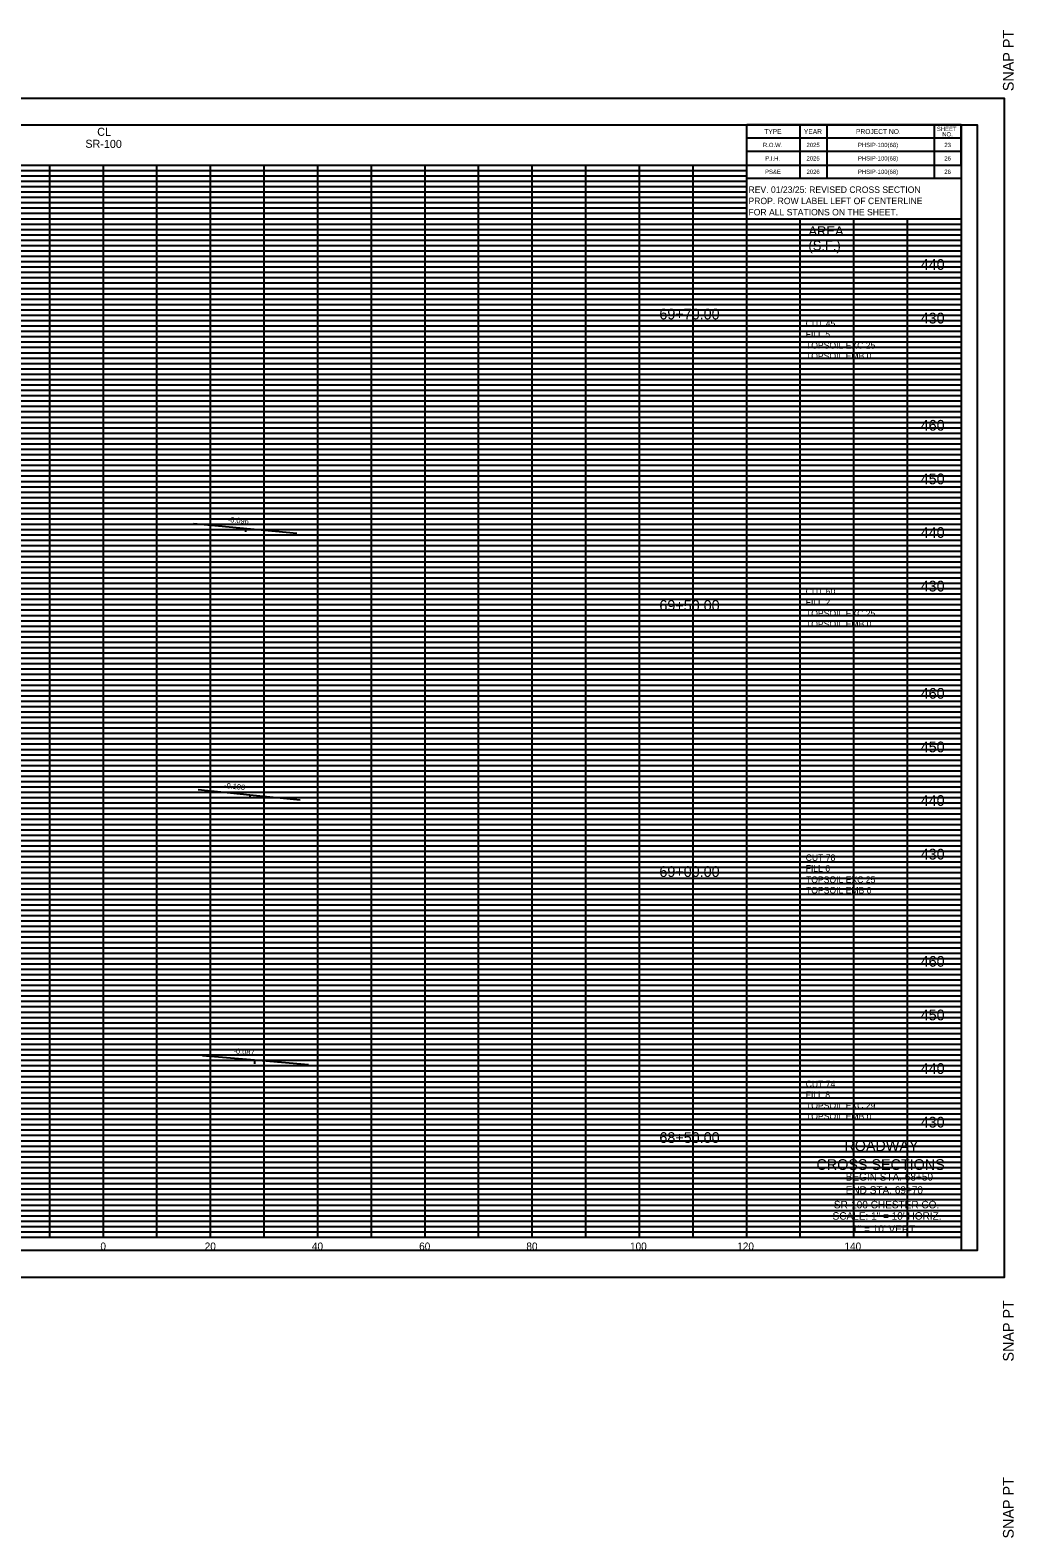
# Model space of a CAD drawing. Extents: x 37 to 1710, y 707 to 2305.
# Drawn here: x 1526.3 to 1709.8, y 1213.9 to 1495.2 of the extents above; entities that cross this region are included whole.
import ezdxf

# ---------------------------------------------------------------- set-up
doc = ezdxf.new("R2010")
doc.units = 0
for name, color, linetype in [('DESIGN - DRAINAGE - Special Ditch Width Text', 7, 'Continuous'), ('DESIGN - SCRATCH - User 1', 7, 'Continuous'), ('DESIGN - SHEET - Corner Text', 7, 'Continuous'), ('DESIGN - SHEET - Light Grid', 7, 'Continuous'), ('DESIGN - SHEET - Linework', 7, 'Continuous'), ('DESIGN - SHEET - Plot Shape', 7, 'Continuous'), ('DESIGN - TITLE SHEET - PROJECT LENGTH - ROW', 7, 'Continuous'), ('DESIGN - TYPICAL - Finished Grade and Subgrade', 7, 'Continuous'), ('DESIGN - TYPICAL - Finished Grade Slopes Text', 7, 'Continuous'), ('DESIGN - TYPICAL - Text', 7, 'Continuous')]:
    doc.layers.add(name, color=color, linetype=linetype)

msp = doc.modelspace()

# ---------------------------------------------------------------- linework, layer by layer
at = {"layer": 'DESIGN - SCRATCH - User 1'}
for p, q in [((1665, 1473.75), (1665, 1473.75)), ((1665, 1471.25), (1665, 1471.25)), ((1672.5, 1473.75), (1672.5, 1473.75)), ((1672.5, 1471.25), (1672.5, 1471.25)), ((1685, 1473.75), (1685, 1473.75)), ((1685, 1471.25), (1685, 1471.25)), ((1697.5, 1473.75), (1697.5, 1473.75)), ((1697.5, 1471.25), (1697.5, 1471.25))]:
    msp.add_line(p, q, dxfattribs=at)
at = {"layer": 'DESIGN - SHEET - Light Grid'}
for p, q in [((1380, 1469), (1660, 1469)), ((1380, 1468), (1660, 1468)), ((1380, 1467), (1660, 1467)), ((1380, 1466), (1660, 1466)), ((1380, 1465), (1660, 1465)), ((1380, 1464), (1660, 1464)), ((1380, 1463), (1660, 1463)), ((1380, 1462), (1660, 1462)), ((1380, 1461), (1660, 1461)), ((1380, 1459), (1700, 1459)), ((1380, 1458), (1700, 1458)), ((1380, 1457), (1700, 1457)), ((1380, 1456), (1700, 1456)), ((1380, 1455), (1700, 1455)), ((1380, 1454), (1700, 1454)), ((1380, 1453), (1700, 1453)), ((1380, 1452), (1700, 1452)), ((1380, 1451), (1700, 1451)), ((1380, 1449), (1700, 1449)), ((1380, 1448), (1700, 1448)), ((1380, 1447), (1700, 1447)), ((1380, 1446), (1700, 1446)), ((1380, 1445), (1700, 1445)), ((1380, 1444), (1700, 1444)), ((1380, 1443), (1700, 1443)), ((1380, 1442), (1700, 1442)), ((1380, 1441), (1700, 1441)), ((1380, 1439), (1700, 1439)), ((1380, 1438), (1700, 1438)), ((1380, 1437), (1700, 1437)), ((1380, 1436), (1700, 1436)), ((1380, 1435), (1700, 1435)), ((1380, 1434), (1700, 1434)), ((1380, 1433), (1700, 1433)), ((1380, 1432), (1700, 1432)), ((1380, 1431), (1700, 1431)), ((1380, 1429), (1700, 1429)), ((1380, 1428), (1700, 1428)), ((1380, 1427), (1700, 1427)), ((1380, 1426), (1700, 1426)), ((1380, 1425), (1700, 1425)), ((1380, 1424), (1700, 1424)), ((1380, 1423), (1700, 1423)), ((1380, 1422), (1700, 1422)), ((1380, 1421), (1700, 1421)), ((1380, 1419), (1700, 1419)), ((1380, 1418), (1700, 1418)), ((1380, 1417), (1700, 1417)), ((1380, 1416), (1700, 1416)), ((1380, 1415), (1700, 1415)), ((1380, 1414), (1700, 1414)), ((1380, 1413), (1700, 1413)), ((1380, 1412), (1700, 1412)), ((1380, 1411), (1700, 1411)), ((1380, 1409), (1700, 1409)), ((1380, 1408), (1700, 1408)), ((1380, 1407), (1700, 1407)), ((1380, 1406), (1700, 1406)), ((1380, 1405), (1700, 1405)), ((1380, 1404), (1700, 1404)), ((1380, 1403), (1700, 1403)), ((1380, 1402), (1700, 1402)), ((1380, 1401), (1700, 1401)), ((1380, 1399), (1700, 1399)), ((1380, 1398), (1700, 1398)), ((1380, 1397), (1700, 1397)), ((1380, 1396), (1700, 1396)), ((1380, 1395), (1700, 1395)), ((1380, 1394), (1700, 1394)), ((1380, 1393), (1700, 1393)), ((1380, 1392), (1700, 1392)), ((1380, 1391), (1700, 1391)), ((1380, 1389), (1700, 1389)), ((1380, 1388), (1700, 1388)), ((1380, 1387), (1700, 1387)), ((1380, 1386), (1700, 1386)), ((1380, 1385), (1700, 1385)), ((1380, 1384), (1700, 1384)), ((1380, 1383), (1700, 1383)), ((1380, 1382), (1700, 1382)), ((1380, 1381), (1700, 1381)), ((1380, 1379), (1700, 1379)), ((1380, 1378), (1700, 1378)), ((1380, 1377), (1700, 1377)), ((1380, 1376), (1700, 1376)), ((1380, 1375), (1700, 1375)), ((1380, 1374), (1700, 1374)), ((1380, 1373), (1700, 1373)), ((1380, 1372), (1700, 1372)), ((1380, 1371), (1700, 1371)), ((1380, 1369), (1700, 1369)), ((1380, 1368), (1700, 1368)), ((1380, 1367), (1700, 1367)), ((1380, 1366), (1700, 1366)), ((1380, 1365), (1700, 1365)), ((1380, 1364), (1700, 1364)), ((1380, 1363), (1700, 1363)), ((1380, 1362), (1700, 1362)), ((1380, 1361), (1700, 1361)), ((1380, 1359), (1700, 1359)), ((1380, 1358), (1700, 1358)), ((1380, 1357), (1700, 1357)), ((1380, 1356), (1700, 1356)), ((1380, 1355), (1700, 1355)), ((1380, 1354), (1700, 1354)), ((1380, 1353), (1700, 1353)), ((1380, 1352), (1700, 1352)), ((1380, 1351), (1700, 1351)), ((1380, 1349), (1700, 1349)), ((1380, 1348), (1700, 1348)), ((1380, 1347), (1700, 1347)), ((1380, 1346), (1700, 1346)), ((1380, 1345), (1700, 1345)), ((1380, 1344), (1700, 1344)), ((1380, 1343), (1700, 1343)), ((1380, 1342), (1700, 1342)), ((1380, 1341), (1700, 1341)), ((1380, 1339), (1700, 1339)), ((1380, 1338), (1700, 1338)), ((1380, 1337), (1700, 1337)), ((1380, 1336), (1700, 1336)), ((1380, 1335), (1700, 1335)), ((1380, 1334), (1700, 1334)), ((1380, 1333), (1700, 1333)), ((1380, 1332), (1700, 1332)), ((1380, 1331), (1700, 1331)), ((1380, 1329), (1700, 1329)), ((1380, 1328), (1700, 1328)), ((1380, 1327), (1700, 1327)), ((1380, 1326), (1700, 1326)), ((1380, 1325), (1700, 1325)), ((1380, 1324), (1700, 1324)), ((1380, 1323), (1700, 1323)), ((1380, 1322), (1700, 1322)), ((1380, 1321), (1700, 1321)), ((1380, 1319), (1700, 1319)), ((1380, 1318), (1700, 1318)), ((1380, 1317), (1700, 1317)), ((1380, 1316), (1700, 1316)), ((1380, 1315), (1700, 1315)), ((1380, 1314), (1700, 1314)), ((1380, 1313), (1700, 1313)), ((1380, 1312), (1700, 1312)), ((1380, 1311), (1700, 1311)), ((1380, 1309), (1700, 1309)), ((1380, 1308), (1700, 1308)), ((1380, 1307), (1700, 1307)), ((1380, 1306), (1700, 1306)), ((1380, 1305), (1700, 1305)), ((1380, 1304), (1700, 1304)), ((1380, 1303), (1700, 1303)), ((1380, 1302), (1700, 1302)), ((1380, 1301), (1700, 1301)), ((1380, 1299), (1700, 1299)), ((1380, 1298), (1700, 1298)), ((1380, 1297), (1700, 1297)), ((1380, 1296), (1700, 1296)), ((1380, 1295), (1700, 1295)), ((1380, 1294), (1700, 1294)), ((1380, 1293), (1700, 1293)), ((1380, 1292), (1700, 1292)), ((1380, 1291), (1700, 1291)), ((1380, 1289), (1700, 1289)), ((1380, 1288), (1700, 1288)), ((1380, 1287), (1700, 1287)), ((1380, 1286), (1700, 1286)), ((1380, 1285), (1700, 1285)), ((1380, 1284), (1700, 1284)), ((1380, 1283), (1700, 1283)), ((1380, 1282), (1700, 1282)), ((1380, 1281), (1700, 1281)), ((1380, 1279), (1700, 1279)), ((1380, 1278), (1700, 1278)), ((1380, 1277), (1700, 1277)), ((1380, 1276), (1700, 1276)), ((1380, 1275), (1700, 1275)), ((1380, 1274), (1700, 1274)), ((1380, 1273), (1700, 1273)), ((1380, 1272), (1700, 1272)), ((1380, 1271), (1700, 1271))]:
    msp.add_line(p, q, dxfattribs=at)
at = {"layer": 'DESIGN - SHEET - Linework'}
for p, q in [((1700, 1477.5), (1660, 1477.5)), ((1660, 1470), (1660, 1477.5)), ((1670, 1467.5), (1670, 1477.5)), ((1675, 1467.5), (1675, 1477.5)), ((1695, 1467.5), (1695, 1477.5)), ((1700, 1470), (1700, 1477.5)), ((1700, 1475), (1660, 1475)), ((1700, 1472.5), (1660, 1472.5)), ((1380, 1470), (1700, 1470)), ((1530, 1270), (1530, 1470)), ((1540, 1270), (1540, 1470)), ((1550, 1270), (1550, 1470)), ((1560, 1270), (1560, 1470)), ((1570, 1270), (1570, 1470)), ((1580, 1270), (1580, 1470)), ((1590, 1270), (1590, 1470)), ((1600, 1270), (1600, 1470)), ((1610, 1270), (1610, 1470)), ((1620, 1270), (1620, 1470)), ((1630, 1270), (1630, 1470)), ((1640, 1270), (1640, 1470)), ((1650, 1270), (1650, 1470)), ((1660, 1270), (1660, 1470)), ((1700, 1467.5), (1660, 1467.5)), ((1380, 1460), (1700, 1460)), ((1670, 1270), (1670, 1460)), ((1680, 1270), (1680, 1460)), ((1690, 1270), (1690, 1460)), ((1380, 1450), (1700, 1450)), ((1380, 1440), (1700, 1440)), ((1380, 1430), (1700, 1430)), ((1380, 1420), (1700, 1420)), ((1380, 1410), (1700, 1410)), ((1380, 1400), (1700, 1400)), ((1380, 1390), (1700, 1390)), ((1380, 1380), (1700, 1380)), ((1380, 1370), (1700, 1370)), ((1380, 1360), (1700, 1360)), ((1380, 1350), (1700, 1350)), ((1380, 1340), (1700, 1340)), ((1380, 1330), (1700, 1330)), ((1380, 1320), (1700, 1320)), ((1380, 1310), (1700, 1310)), ((1380, 1300), (1700, 1300)), ((1380, 1290), (1700, 1290)), ((1380, 1280), (1700, 1280)), ((1380, 1270), (1700, 1270))]:
    msp.add_line(p, q, dxfattribs=at)
for points in [[(1368, 1482.5), (1708, 1482.5), (1708, 1262.5), (1368, 1262.5)], [(1380, 1477.5), (1700, 1477.5), (1700, 1267.5), (1380, 1267.5)]]:
    msp.add_lwpolyline(points, close=True, dxfattribs=at)
at = {"layer": 'DESIGN - SHEET - Plot Shape'}
msp.add_lwpolyline([(1373, 1477.5), (1703, 1477.5), (1703, 1267.5), (1373, 1267.5)], close=True, dxfattribs=at)
at = {"layer": 'DESIGN - TYPICAL - Finished Grade and Subgrade'}
for p, q in [((1556.84, 1403.16), (1576.09, 1401.31)), ((1566.52, 1402.23), (1566.52, 1401.55)), ((1557.67, 1353.51), (1567.35, 1352.54)), ((1567.35, 1352.54), (1567.35, 1351.9)), ((1567.35, 1352.54), (1576.7, 1351.61)), ((1558.5, 1303.92), (1568.18, 1303.08)), ((1568.18, 1303.08), (1568.18, 1302.31)), ((1568.18, 1303.08), (1578.28, 1302.2))]:
    msp.add_line(p, q, dxfattribs=at)

# ---------------------------------------------------------------- texts
at = {"layer": 'DESIGN - DRAINAGE - Special Ditch Width Text'}
for s, p in [('CL', (1538.85, 1475.46)), ('SR-100', (1536.64, 1473.23))]:
    msp.add_text(s, height=1.5, rotation=359.6675, dxfattribs=at).set_placement(p)
at = {"layer": 'DESIGN - SHEET - Corner Text'}
for s, p in [('  SNAP PT', (1709.8, 1482.3)), ('SNAP PT  ', (1709.8, 1246.8)), ('  SNAP PT', (1709.8, 1212.3))]:
    msp.add_text(s, height=2, rotation=90, dxfattribs=at).set_placement(p)
for s, height, p in [('R.O.W.', 0.8, (1663.02, 1473.35)), ('2025', 0.8, (1671.16, 1473.35)), ('PHSIP-100(68)', 0.8, (1680.75, 1473.35)), ('23', 0.8, (1696.86, 1473.35)), ('P.I.H.', 0.8, (1663.45, 1470.85)), ('2025', 0.8, (1671.16, 1470.85)), ('PHSIP-100(68)', 0.8, (1680.75, 1470.85)), ('26', 0.8, (1696.86, 1470.85)), ('PS&E', 0.8, (1663.42, 1468.35)), ('2026', 0.8, (1671.16, 1468.35)), ('PHSIP-100(68)', 0.8, (1680.75, 1468.35)), ('26', 0.8, (1696.86, 1468.35)), ('ROADWAY ', 2, (1678.23, 1286.05)), ('CROSS SECTIONS', 2, (1673.01, 1282.55)), ('BEGIN STA. 68+50', 1.4, (1678.47, 1280.55)), ('END STA. 69+70', 1.4, (1678.47, 1278.1)), ('SCALE: 1" = 10\' HORIZ.', 1.4, (1676.02, 1273.26)), ('SR-100 CHESTER CO.', 1.4, (1676.25, 1275.37)), ('       1" = 10\' VERT.   ', 1.4, (1676.02, 1270.81))]:
    msp.add_text(s, height=height, dxfattribs=at).set_placement(p)
at = {"layer": 'DESIGN - SHEET - Light Grid'}
for s, height, p in [('TYPE', 0.9, (1663.26, 1475.8)), ('YEAR', 0.9, (1670.66, 1475.8)), ('PROJECT NO.', 0.9, (1680.38, 1475.8)), ('SHEET', 0.8, (1695.47, 1476.35)), ('NO.', 0.8, (1696.47, 1475.35))]:
    msp.add_text(s, height=height, dxfattribs=at).set_placement(p)
at = {"layer": 'DESIGN - TITLE SHEET - PROJECT LENGTH - ROW'}
for s, p in [('REV. 01/23/25: REVISED CROSS SECTION ', (1660.33, 1464.81)), ('PROP. ROW LABEL LEFT OF CENTERLINE ', (1660.33, 1462.71)), ('FOR ALL STATIONS ON THE SHEET.', (1660.33, 1460.61))]:
    msp.add_text(s, height=1.2, rotation=0, dxfattribs=at).set_placement(p)
at = {"layer": 'DESIGN - TYPICAL - Finished Grade Slopes Text'}
for s, rotation, p in [('-0.096', 354.5004, (1563.18, 1403.4)), ('-0.100', 354.2756, (1562.49, 1353.79)), ('-0.087', 355.0215, (1564.25, 1304.27))]:
    msp.add_text(s, height=1, rotation=rotation, dxfattribs=at).set_placement(p)
at = {"layer": 'DESIGN - TYPICAL - Text'}
for s, height, p in [('AREA ', 1.8, (1671.52, 1456.79)), ('(S.F.)', 1.8, (1671.52, 1454.09)), ('     440     ', 2, (1688.74, 1450.45)), ('     69+70.00     ', 2, (1640, 1441.21)), ('CUT 45', 1.2, (1671, 1439.84)), ('     430     ', 2, (1688.74, 1440.45)), ('FILL 5', 1.2, (1671, 1437.84)), ('TOPSOIL EXC 25', 1.2, (1671.06, 1435.77)), ('TOPSOIL EMB 0', 1.2, (1671.06, 1433.78)), ('     460     ', 2, (1688.74, 1420.45)), ('     450     ', 2, (1688.74, 1410.45)), ('     440     ', 2, (1688.74, 1400.45)), ('     430     ', 2, (1688.74, 1390.45)), ('CUT 60', 1.2, (1671, 1389.84)), ('     69+50.00     ', 2, (1640, 1386.84)), ('TOPSOIL EXC 25', 1.2, (1671.06, 1385.77)), ('FILL 2', 1.2, (1671, 1387.84)), ('TOPSOIL EMB 0', 1.2, (1671.06, 1383.78)), ('     460     ', 2, (1688.74, 1370.45)), ('     450     ', 2, (1688.74, 1360.45)), ('     440     ', 2, (1688.74, 1350.45)), ('     430     ', 2, (1688.74, 1340.45)), ('     69+00.00     ', 2, (1640, 1337.2)), ('CUT 78', 1.2, (1671, 1340.2)), ('FILL 6', 1.2, (1671, 1338.2)), ('TOPSOIL EXC 25', 1.2, (1671.06, 1336.1)), ('TOPSOIL EMB 0', 1.2, (1671.06, 1334.12)), ('     460     ', 2, (1688.74, 1320.45)), ('     450     ', 2, (1688.74, 1310.45)), ('     440     ', 2, (1688.74, 1300.45)), ('CUT 74', 1.2, (1671, 1297.99)), ('FILL 8', 1.2, (1671, 1295.99)), ('TOPSOIL EXC 29', 1.2, (1671.06, 1293.95)), ('TOPSOIL EMB 0', 1.2, (1671.06, 1291.96)), ('     430     ', 2, (1688.74, 1290.45)), ('     68+50.00     ', 2, (1640, 1287.58)), ('     0     ', 1.4, (1536.85, 1267.6)), ('     0     ', 1.4, (1536.85, 1267.6)), ('     20     ', 1.4, (1556.3, 1267.6)), ('     40     ', 1.4, (1576.3, 1267.6)), ('     60     ', 1.4, (1596.3, 1267.6)), ('     80     ', 1.4, (1616.3, 1267.6)), ('     100     ', 1.4, (1635.63, 1267.6)), ('     120     ', 1.4, (1655.63, 1267.6)), ('     140     ', 1.4, (1675.63, 1267.6))]:
    msp.add_text(s, height=height, dxfattribs=at).set_placement(p)

doc.saveas('drawing.dxf')
